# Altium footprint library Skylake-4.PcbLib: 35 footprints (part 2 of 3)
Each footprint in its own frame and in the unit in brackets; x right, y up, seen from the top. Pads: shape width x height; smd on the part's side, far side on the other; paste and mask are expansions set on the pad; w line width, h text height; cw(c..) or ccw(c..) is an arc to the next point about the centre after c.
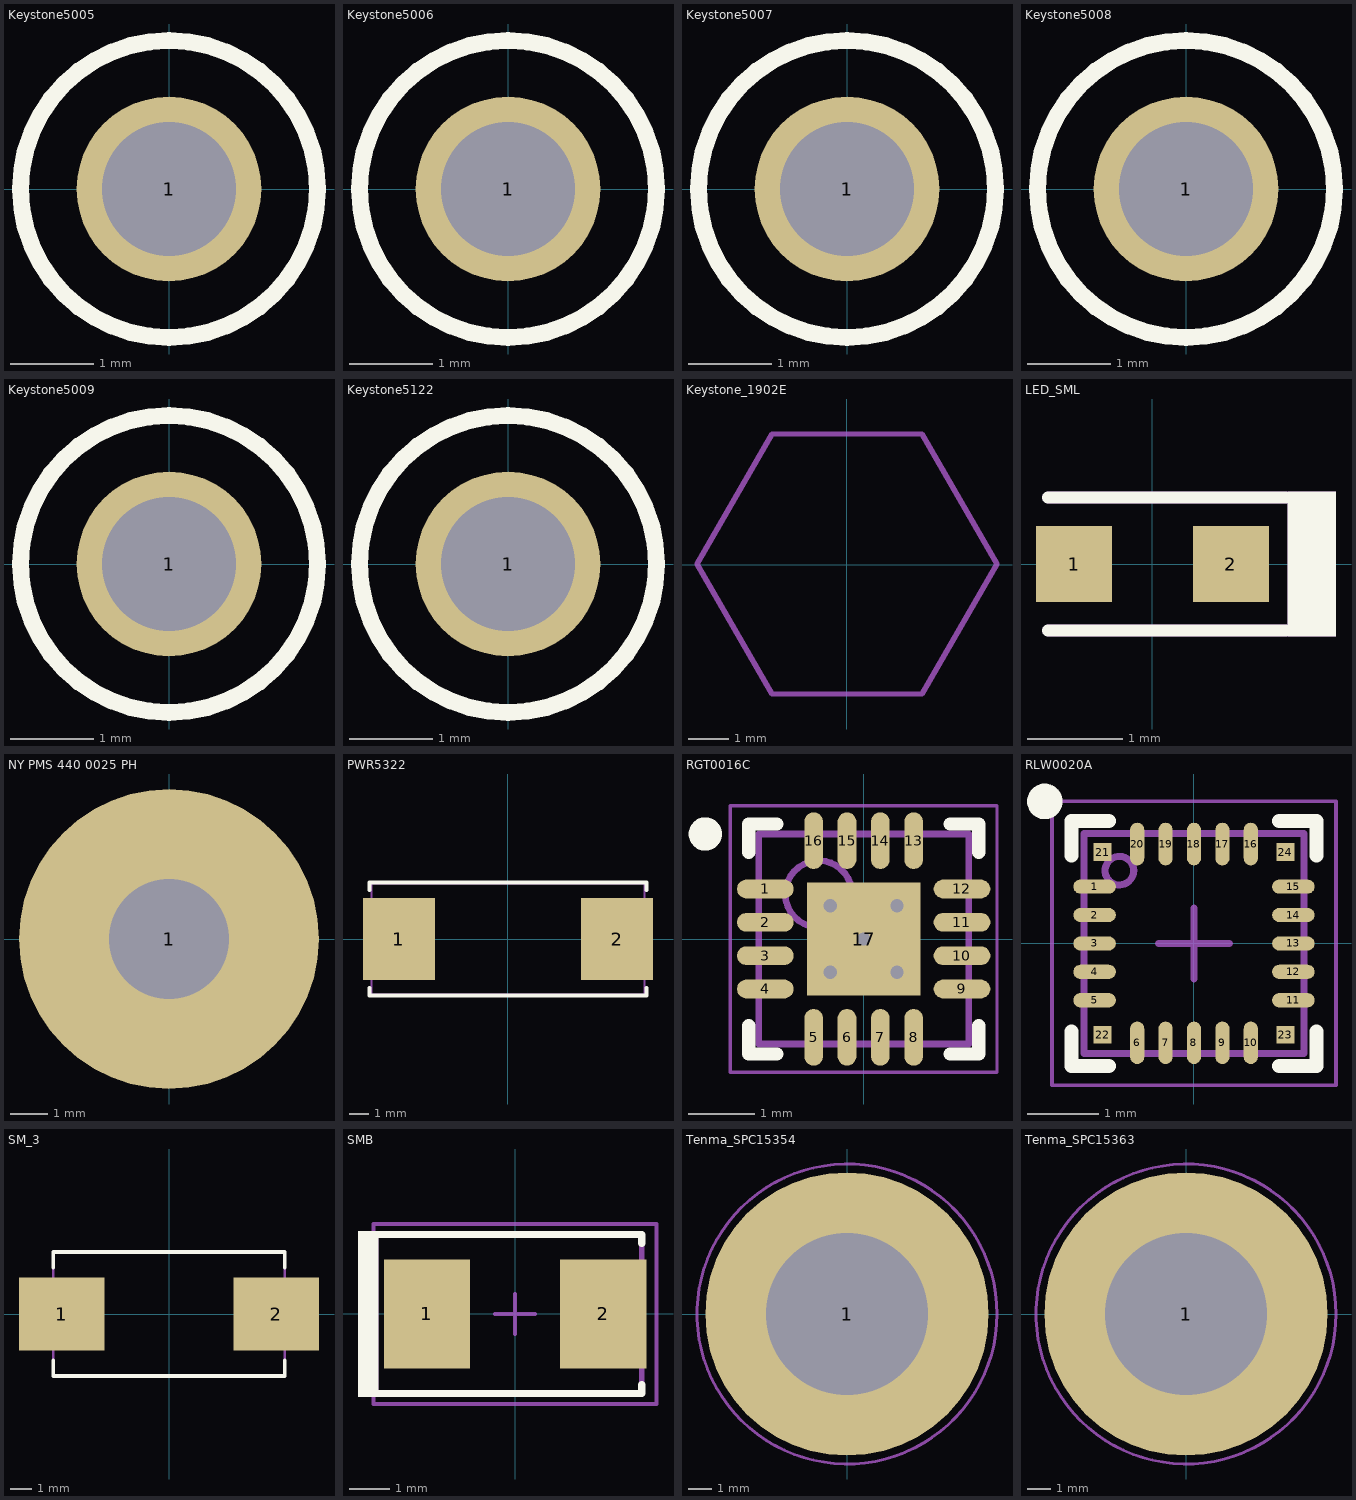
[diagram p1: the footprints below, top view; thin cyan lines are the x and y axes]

## Keystone5005 [mil] "Keystone Compact loops"
height 220
pads (1):
  round 87 hole 63: 1(0,0)
Top Overlay:
  circle w7.99: c0,0 r70
Mechanical 5:
  circle w5: c0,0 r70.71
  text ".Designator" at -7.6,-90.13 h30
3D body: height 225.2, standoff -129.92, extent -63,-63 62.49,62.74

## Keystone5006 [mil] "Keystone Compact loops"
height 220
pads (1):
  round 87 hole 63: 1(0,0)
Top Overlay:
  circle w7.99: c0,0 r70
Mechanical 5:
  circle w5: c0,0 r70.71
  text ".Designator" at -31.57,-8.13 h30
3D body: height 225.2, standoff -129.92, extent -63,-63 62.49,62.74

## Keystone5007 [mil] "Keystone Compact loops"
height 220
pads (1):
  round 87 hole 63: 1(0,0)
Top Overlay:
  circle w7.99: c0,0 r70
Mechanical 5:
  circle w5: c0,0 r70.71
  text ".Designator" at 84.03,-1.97 h30
3D body: height 225.2, standoff -129.92, extent -63,-63 62.49,62.74

## Keystone5008 [mil] "Keystone Compact loops"
height 220
pads (1):
  round 87 hole 63: 1(0,0)
Top Overlay:
  circle w7.99: c0,0 r70
Mechanical 5:
  circle w5: c0,0 r70.71
  text ".Designator" at 84.02,-35.28 h30
3D body: height 225.2, standoff -129.92, extent -63,-63 62.49,62.74

## Keystone5009 [mil] "Keystone Compact loops"
height 220
pads (1):
  round 87 hole 63: 1(0,0)
Top Overlay:
  circle w7.99: c0,0 r70
Mechanical 5:
  circle w5: c0,0 r70.71
  text ".Designator" at 85.67,-16.13 h30
3D body: height 225.2, standoff -129.92, extent -63,-63 62.49,62.74

## Keystone5122 [mil] "Keystone Compact loops"
height 220
pads (1):
  round 87 hole 63: 1(0,0)
Top Overlay:
  circle w7.99: c0,0 r70
Mechanical 5:
  circle w5: c0,0 r70.71
  text ".Designator" at -8.08,45.77 h30
3D body: height 225.2, standoff -129.92, extent -63,-63 62.49,62.74

## Keystone_1902E [mil] "Hex Standoff, 4-40 threaded, nylon"
height 1000
pads (1):
  round 1 on Mech3: 0(0,0)
Mechanical 5:
  lines w5: -145.29,0.49 -72.56,-125.49 72.92,-125.49 145.65,0.49 72.92,126.47 -72.56,126.47 -145.29,0.49
  text ".Designator" at -60,-20 h30
3D body: height 1001, standoff 1, extent -144.95,-125.98 146,125.98

## LED_SML [mm] "Rohm"
height 0.9
pads (2):
  rect 0.8x0.8 smd: 1(-0.825,0) 2(0.825,0)
Top Overlay:
  rectangle: 1.422,-0.762 1.93,0.762
  lines w0.127: -1.1,-0.7 1.4,-0.7 ; -1.1,0.7 1.4,0.7
Mechanical 5:
  rectangle: 1.422,-0.762 1.93,0.762
  lines w0.127: -1.1,-0.7 1.626,-0.7 ; -1.1,0.7 1.626,0.7
  text ".Designator" at 0.553,0.2 h0.6
3D body: height 0.25, standoff 0, extent -0.8,-0.4 0.8,0.4
3D body: height 0.9, standoff 0.25, extent -0.6,-0.4 0.6,0.4

## NY PMS 440 0025 PH [mm] "4-40 nylon screw and mounting hole"
height 1.905
pads (1):
  round 8 hole 3.2: 1(0,0)
Mechanical 5:
  circle w0.127: c0,0 r3.789
  text ".Designator" at -1.524,-0.508 h0.76
3D body: height 2.69, standoff -8.74, extent -3.302,-3.3 3.296,3.3

## PWR5322 [mm] "BOURNS"
height 5.879
pads (2):
  rect 3.7x4.2 smd: 1(-5.6,0) 2(5.6,0)
Top Overlay:
  lines w0.2: -7.1,-2.5 -7.1,-2.9 7.1,-2.9 7.1,-2.5 ; -7.1,2.5 -7.1,2.9 7.1,2.9 7.1,2.5
Mechanical 5:
  lines w0.1: -7.015,-2.859 -7.015,2.859 7.015,2.859 7.015,-2.859 -7.015,-2.859
  text ".Designator" at 0.143,-0.235 h0.76
3D body: height 5.88, standoff 0, extent -7.014,-2.858 7.014,2.858

## RGT0016C [mm] "QFN, 16-Leads, Body 3x3mm, Pitch 0.5mm, Thermal Pad 1.7x1.7mm, TI Recommended"
height 1
pads (17):
  oval 0.85x0.28 smd paste-0.025 mask+0.013: 1(-1.475,0.75) 2(-1.475,0.25) 3(-1.475,-0.25) 4(-1.475,-0.75) 9(1.475,-0.75) 10(1.475,-0.25) 11(1.475,0.25) 12(1.475,0.75)
  oval 0.28x0.85 smd paste-0.025 mask+0.013: 5(-0.75,-1.475) 6(-0.25,-1.475) 7(0.25,-1.475) 8(0.75,-1.475) 13(0.75,1.475) 14(0.25,1.475) 15(-0.25,1.475) 16(-0.75,1.475)
  rect 1.7x1.7 smd paste-0.85 mask+0.013: 17(0,0)
via -0.5,0.5 diameter 0.5 hole 0.2
via -0.5,-0.5 diameter 0.5 hole 0.2
via 0.5,-0.5 diameter 0.5 hole 0.2
via 0.5,0.5 diameter 0.5 hole 0.2
via 0,0 diameter 0.5 hole 0.2
Top Overlay:
  circle w0.25: c-2.375,1.575 r0.125
  lines w0.2: -1.725,-1.3 -1.725,-1.725 -1.3,-1.725 ; -1.725,1.3 -1.725,1.725 -1.3,1.725 ; 1.3,-1.725 1.725,-1.725 1.725,-1.3 ; 1.3,1.725 1.725,1.725 1.725,1.3
Top Paste:
  region: -0.1,0.1 -0.1,0.8 -0.8,0.8 -0.8,0.1
  region: -0.1,-0.1 -0.8,-0.1 -0.8,-0.8 -0.1,-0.8
  region: 0.1,-0.1 0.1,-0.8 0.8,-0.8 0.8,-0.1
  rectangle: 0.1,0.1 0.8,0.8
Mechanical 5:
  circle w0.1: c-0.675,0.675 r0.5
  lines w0.1: -1.575,-1.575 -1.575,1.575 1.575,1.575 1.575,-1.575 -1.575,-1.575
  text ".Designator" at -0.442,-0.813 h0.76
Mechanical 15:
  lines w0.05: -2,-2 -2,2 2,2 2,-2 -2,-2
  lines w0.1: -0.5,0 0.5,0 ; 0,-0.5 0,0.5
3D body: height 1, standoff 0, extent -1.575,-1.575 1.575,1.575

## RLW0020A [mm] "QFN, 20-Leads, Body 3x3mm, Pitch 0.4mm, TI Recommended"
height 0.8
pads (24):
  oval 0.6x0.2 smd mask+0.045: 1(-1.4,0.8) 2(-1.4,0.4) 3(-1.4,0) 4(-1.4,-0.4) 5(-1.4,-0.8) 11(1.4,-0.8) 12(1.4,-0.4) 13(1.4,0) 14(1.4,0.4) 15(1.4,0.8)
  oval 0.2x0.6 smd mask+0.045: 6(-0.8,-1.4) 7(-0.4,-1.4) 8(0,-1.4) 9(0.4,-1.4) 10(0.8,-1.4) 16(0.8,1.4) 17(0.4,1.4) 18(0,1.4) 19(-0.4,1.4) 20(-0.8,1.4)
  rect 0.25x0.25 smd mask+0.045: 21(-1.288,1.288) 22(-1.288,-1.288) 23(1.288,-1.288) 24(1.288,1.288)
Top Overlay:
  circle w0.25: c-2.1,2 r0.125
  lines w0.2: -1.725,-1.24 -1.725,-1.725 -1.2,-1.725 ; -1.725,1.24 -1.725,1.725 -1.2,1.725 ; 1.2,-1.725 1.725,-1.725 1.725,-1.24 ; 1.2,1.725 1.725,1.725 1.725,1.24
Mechanical 5:
  circle w0.1: c-1.05,1.025 r0.202
  lines w0.1: -1.55,-1.55 1.55,-1.55 1.55,1.55 -1.55,1.55 -1.55,-1.55
  text ".Designator" at -0.325,-0.346 h0.64
Mechanical 15:
  lines w0.05: -2,-2 2,-2 2,2 -2,2 -2,-2
  lines w0.1: -0.5,0 0.5,0 ; 0,-0.5 0,0.5
3D body: height 0.8, standoff 0, extent -1.549,-1.549 1.549,1.549
3D body: height 0.81, standoff 0.7, extent -1.255,0.82 -0.845,1.23

## SM_3 [mm] "TE Connectivity"
height 5.3
pads (2):
  rect 4x3.4 smd: 1(-5,0) 2(5,0)
Top Overlay:
  lines w0.178: -5.4,-2.159 -5.4,-2.9 5.4,-2.9 5.4,-2.159 ; -5.4,2.159 -5.4,2.9 5.4,2.9 5.4,2.159
Mechanical 5:
  lines w0.1: -5.4,-2.9 -5.4,2.9 5.4,2.9 5.4,-2.9 -5.4,-2.9
  text ".Designator" at -0.181,-0.272 h0.76
3D body: height 5.3, standoff 0, extent -5.4,-2.9 5.4,2.9

## SMB [mm] "Molded Diode, 2-Leads, Body 5.4x3.6mm, IPC Medium Density, based on OnSemi component dimensions"
height 2.45
pads (2):
  rect 2.159x2.743 smd: 1(-2.21,0) 2(2.21,0)
Top Overlay:
  rectangle: -3.937,-2.083 -3.429,2.083
  lines w0.178: -3.607,-1.994 3.175,-1.994 3.175,-1.765 ; -3.607,1.994 3.175,1.994 3.175,1.765
Mechanical 5:
  rectangle: -3.937,-2.083 -3.429,2.083
  lines w0.127: -3.607,-1.994 3.175,-1.994 3.175,-1.765 3.175,1.765 3.175,1.994 -3.607,1.994
  text ".Designator" at 0.198,0.382 h0.76
Mechanical 15:
  lines w0.1: -0.5,0 0.5,0 ; 0,-0.5 0,0.5 ; -3.55,-2.25 3.55,-2.25 3.55,2.25 -3.55,2.25 -3.55,-2.25
3D body: height 2.32, standoff 0.02, extent -2.7,-1.8 2.7,1.8

## Tenma_SPC15354 [mm] "Insulated Banana Jack, Black"
height 9.2
pads (1):
  round 12 hole 6.858: 1(0,0)
Mechanical 5:
  circle w0.127: c0,0 r6.35
  text ".Designator" at -0.55,-0.245 h0.76
3D body: height 8.8, standoff -12.42, extent -6.3,-6.337 6.35,6.338

## Tenma_SPC15363 [mm] "Insulated Banana Jack, Red"
height 9.2
pads (1):
  round 12 hole 6.858: 1(0,0)
Mechanical 5:
  circle w0.127: c0,0 r6.35
  text ".Designator" at -1.397,-0.762 h0.76
3D body: height 8.8, standoff -12.42, extent -6.3,-6.337 6.35,6.338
